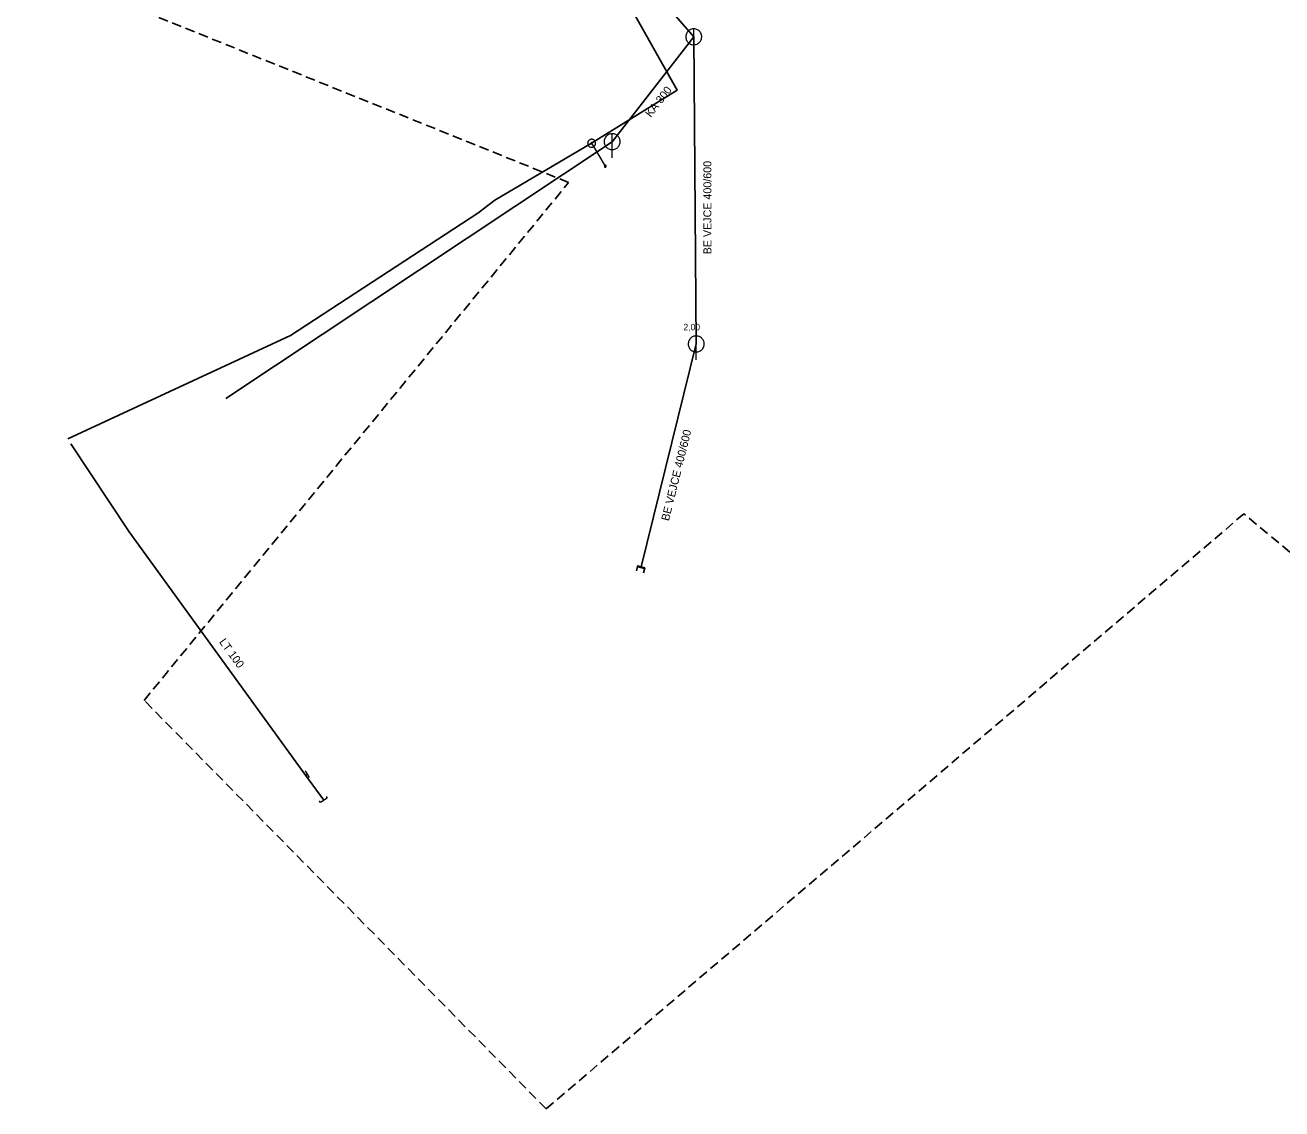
# Model space of a CAD drawing. Extents: x -687195 to -686201, y -974149 to -973877.
# Drawn here: x -687195.2 to -687038.1, y -974149.2 to -974013.8 of the extents above; entities that cross this region are included whole.
import ezdxf

# ---------------------------------------------------------------- set-up
doc = ezdxf.new("R2010")
doc.units = 0
doc.header["$LTSCALE"] = 0.4
doc.linetypes.add('MEDIUM_DASHED', pattern=[4.5, 3, -1.5])
doc.layers.add('1', color=7, linetype='Continuous')
for name, color, linetype, lineweight in [('14', 7, 'Continuous', 25), ('17', 7, 'Continuous', 25), ('22', 7, 'Continuous', 13), ('29', 7, 'Continuous', 13), ('34', 7, 'Continuous', 13), ('47', 7, 'Continuous', 13), ('63', 7, 'MEDIUM_DASHED', 25), ('9', 7, 'Continuous', 13)]:
    doc.layers.add(name, color=color, linetype=linetype, lineweight=lineweight)

msp = doc.modelspace()

# ---------------------------------------------------------------- linework, layer by layer
at = {"layer": '14'}
for p, q in [((-687115.021, -974011.379), (-687111.634, -974015.295)), ((-687111.634, -974015.295), (-687121.836, -974028.397)), ((-687111.634, -974015.295), (-687111.324, -974053.675)), ((-687121.836, -974028.397), (-687170.113, -974060.478)), ((-687111.324, -974053.675), (-687118.2, -974081.535))]:
    msp.add_line(p, q, dxfattribs=at)
at = {"layer": '14', "lineweight": 13}
for p, q in [((-687124.395, -974028.598), (-687122.686, -974031.462)), ((-687160.142, -974107.542), (-687159.94, -974107.42))]:
    msp.add_line(p, q, dxfattribs=at)
at = {"layer": '17'}
for points in [[(-687124.395, -974028.598), (-687113.714, -974021.973), (-687139.989, -973975.271), (-687160.068, -973921.704), (-687165.829, -973892.978), (-687149.548, -973877.175), (-687105.661, -973883.258)], [(-687189.885, -974065.515), (-687162.054, -974052.608), (-687138.614, -974037.32), (-687136.498, -974035.696), (-687124.395, -974028.598)], [(-687189.5, -974066.14), (-687182.219, -974077.149), (-687160.142, -974107.542), (-687157.854, -974110.693)]]:
    msp.add_lwpolyline(points, dxfattribs=at)
at = {"layer": '22'}
for p, q in [((-687111.634, -974017.295), (-687111.633, -974014.295)), ((-687121.836, -974030.397), (-687121.835, -974027.397)), ((-687111.324, -974055.675), (-687111.323, -974052.675))]:
    msp.add_line(p, q, dxfattribs=at)
for points in [[(-687110.634, -974015.295), (-687110.639, -974015.186), (-687110.657, -974015.078), (-687110.687, -974014.972), (-687110.727, -974014.871), (-687110.779, -974014.774), (-687110.841, -974014.684), (-687110.913, -974014.601), (-687110.993, -974014.527), (-687111.081, -974014.461), (-687111.175, -974014.406), (-687111.275, -974014.361), (-687111.38, -974014.328), (-687111.487, -974014.306), (-687111.596, -974014.296), (-687111.706, -974014.298), (-687111.814, -974014.312), (-687111.921, -974014.337), (-687112.024, -974014.374), (-687112.122, -974014.423), (-687112.214, -974014.481), (-687112.3, -974014.55), (-687112.377, -974014.627), (-687112.446, -974014.713), (-687112.505, -974014.805), (-687112.553, -974014.903), (-687112.59, -974015.006), (-687112.616, -974015.113), (-687112.63, -974015.221), (-687112.633, -974015.331), (-687112.623, -974015.44), (-687112.602, -974015.547), (-687112.568, -974015.651), (-687112.524, -974015.751), (-687112.469, -974015.846), (-687112.403, -974015.934), (-687112.329, -974016.014), (-687112.246, -974016.086), (-687112.156, -974016.148), (-687112.06, -974016.2), (-687111.958, -974016.241), (-687111.853, -974016.271), (-687111.745, -974016.289), (-687111.635, -974016.295), (-687111.526, -974016.289), (-687111.418, -974016.271), (-687111.313, -974016.242), (-687111.211, -974016.201), (-687111.114, -974016.149), (-687111.024, -974016.087), (-687110.941, -974016.016), (-687110.866, -974015.936), (-687110.801, -974015.848), (-687110.745, -974015.754), (-687110.701, -974015.654), (-687110.667, -974015.55), (-687110.645, -974015.442), (-687110.635, -974015.333)], [(-687120.836, -974028.397), (-687120.841, -974028.288), (-687120.859, -974028.18), (-687120.889, -974028.074), (-687120.929, -974027.973), (-687120.981, -974027.876), (-687121.043, -974027.786), (-687121.115, -974027.703), (-687121.195, -974027.629), (-687121.283, -974027.563), (-687121.377, -974027.508), (-687121.477, -974027.463), (-687121.582, -974027.43), (-687121.689, -974027.408), (-687121.798, -974027.398), (-687121.908, -974027.4), (-687122.016, -974027.414), (-687122.123, -974027.439), (-687122.226, -974027.476), (-687122.324, -974027.525), (-687122.416, -974027.583), (-687122.502, -974027.652), (-687122.579, -974027.729), (-687122.648, -974027.815), (-687122.707, -974027.907), (-687122.755, -974028.005), (-687122.792, -974028.108), (-687122.818, -974028.215), (-687122.832, -974028.323), (-687122.835, -974028.433), (-687122.825, -974028.542), (-687122.804, -974028.649), (-687122.77, -974028.753), (-687122.726, -974028.853), (-687122.671, -974028.948), (-687122.605, -974029.036), (-687122.531, -974029.116), (-687122.448, -974029.188), (-687122.358, -974029.25), (-687122.262, -974029.302), (-687122.16, -974029.343), (-687122.055, -974029.373), (-687121.947, -974029.391), (-687121.837, -974029.397), (-687121.728, -974029.391), (-687121.62, -974029.373), (-687121.515, -974029.344), (-687121.413, -974029.303), (-687121.316, -974029.251), (-687121.226, -974029.189), (-687121.143, -974029.118), (-687121.068, -974029.038), (-687121.003, -974028.95), (-687120.947, -974028.856), (-687120.903, -974028.756), (-687120.869, -974028.652), (-687120.847, -974028.544), (-687120.837, -974028.435)], [(-687110.324, -974053.675), (-687110.329, -974053.566), (-687110.347, -974053.458), (-687110.377, -974053.352), (-687110.417, -974053.251), (-687110.469, -974053.154), (-687110.531, -974053.064), (-687110.603, -974052.981), (-687110.683, -974052.907), (-687110.771, -974052.841), (-687110.865, -974052.786), (-687110.965, -974052.741), (-687111.07, -974052.708), (-687111.177, -974052.686), (-687111.286, -974052.676), (-687111.396, -974052.678), (-687111.504, -974052.692), (-687111.611, -974052.717), (-687111.714, -974052.754), (-687111.812, -974052.803), (-687111.904, -974052.861), (-687111.99, -974052.93), (-687112.067, -974053.007), (-687112.136, -974053.093), (-687112.195, -974053.185), (-687112.243, -974053.283), (-687112.28, -974053.386), (-687112.306, -974053.493), (-687112.32, -974053.601), (-687112.323, -974053.711), (-687112.313, -974053.82), (-687112.292, -974053.927), (-687112.258, -974054.031), (-687112.214, -974054.131), (-687112.159, -974054.226), (-687112.093, -974054.314), (-687112.019, -974054.394), (-687111.936, -974054.466), (-687111.846, -974054.528), (-687111.75, -974054.58), (-687111.648, -974054.621), (-687111.543, -974054.651), (-687111.435, -974054.669), (-687111.325, -974054.675), (-687111.216, -974054.669), (-687111.108, -974054.651), (-687111.003, -974054.622), (-687110.901, -974054.581), (-687110.804, -974054.529), (-687110.714, -974054.467), (-687110.631, -974054.396), (-687110.556, -974054.316), (-687110.491, -974054.228), (-687110.435, -974054.134), (-687110.391, -974054.034), (-687110.357, -974053.93), (-687110.335, -974053.822), (-687110.325, -974053.713)]]:
    msp.add_lwpolyline(points, close=True, dxfattribs=at)
at = {"layer": '29'}
for points in [[(-687117.865, -974082.256), (-687117.718, -974081.653), (-687118.681, -974081.417), (-687118.829, -974082.022)], [(-687118.744, -974082.042), (-687118.618, -974081.522), (-687117.823, -974081.716), (-687117.95, -974082.236)]]:
    msp.add_lwpolyline(points, dxfattribs=at)
at = {"layer": '34'}
msp.add_line((-687160.199, -974106.992), (-687159.681, -974107.848), dxfattribs=at)
at = {"layer": '47'}
for points in [[(-687123.986, -974028.309), (-687124.019, -974028.268), (-687124.055, -974028.23), (-687124.095, -974028.198), (-687124.138, -974028.168), (-687124.185, -974028.143), (-687124.234, -974028.124), (-687124.284, -974028.111), (-687124.336, -974028.102), (-687124.387, -974028.098), (-687124.44, -974028.1), (-687124.492, -974028.107), (-687124.543, -974028.121), (-687124.592, -974028.138), (-687124.639, -974028.162), (-687124.683, -974028.189), (-687124.724, -974028.222), (-687124.762, -974028.258), (-687124.795, -974028.299), (-687124.824, -974028.341), (-687124.849, -974028.388), (-687124.868, -974028.437), (-687124.882, -974028.488), (-687124.891, -974028.539), (-687124.895, -974028.591), (-687124.892, -974028.643), (-687124.885, -974028.695), (-687124.872, -974028.746), (-687124.854, -974028.795), (-687124.83, -974028.842), (-687124.803, -974028.886), (-687124.77, -974028.927), (-687124.734, -974028.965), (-687124.694, -974028.999), (-687124.651, -974029.027), (-687124.604, -974029.052), (-687124.556, -974029.071), (-687124.505, -974029.086), (-687124.454, -974029.095), (-687124.401, -974029.098), (-687124.349, -974029.095), (-687124.297, -974029.088), (-687124.247, -974029.076), (-687124.197, -974029.057), (-687124.15, -974029.033), (-687124.106, -974029.006), (-687124.065, -974028.973), (-687124.027, -974028.937), (-687123.994, -974028.897), (-687123.965, -974028.854), (-687123.94, -974028.807), (-687123.921, -974028.759), (-687123.907, -974028.709), (-687123.898, -974028.657), (-687123.895, -974028.605), (-687123.897, -974028.552), (-687123.904, -974028.5), (-687123.917, -974028.45), (-687123.935, -974028.4), (-687123.959, -974028.353)], [(-687124.328, -974028.55), (-687124.333, -974028.543), (-687124.339, -974028.537), (-687124.345, -974028.532), (-687124.352, -974028.527), (-687124.36, -974028.523), (-687124.368, -974028.52), (-687124.376, -974028.517), (-687124.385, -974028.516), (-687124.393, -974028.516), (-687124.402, -974028.516), (-687124.411, -974028.517), (-687124.419, -974028.519), (-687124.427, -974028.522), (-687124.434, -974028.525), (-687124.442, -974028.531), (-687124.449, -974028.536), (-687124.455, -974028.542), (-687124.46, -974028.548), (-687124.465, -974028.555), (-687124.469, -974028.563), (-687124.472, -974028.571), (-687124.475, -974028.579), (-687124.476, -974028.588), (-687124.477, -974028.597), (-687124.476, -974028.605), (-687124.475, -974028.614), (-687124.473, -974028.622), (-687124.47, -974028.63), (-687124.467, -974028.637), (-687124.461, -974028.645), (-687124.456, -974028.652), (-687124.45, -974028.658), (-687124.444, -974028.663), (-687124.437, -974028.668), (-687124.429, -974028.672), (-687124.422, -974028.675), (-687124.413, -974028.678), (-687124.404, -974028.679), (-687124.395, -974028.68), (-687124.387, -974028.679), (-687124.378, -974028.678), (-687124.37, -974028.676), (-687124.362, -974028.673), (-687124.355, -974028.67), (-687124.347, -974028.664), (-687124.34, -974028.659), (-687124.334, -974028.653), (-687124.329, -974028.647), (-687124.324, -974028.64), (-687124.32, -974028.632), (-687124.317, -974028.625), (-687124.314, -974028.616), (-687124.313, -974028.607), (-687124.313, -974028.599), (-687124.313, -974028.59), (-687124.314, -974028.581), (-687124.316, -974028.573), (-687124.319, -974028.565), (-687124.322, -974028.558)]]:
    msp.add_lwpolyline(points, close=True, dxfattribs=at)
msp.add_lwpolyline([(-687157.576, -974110.21), (-687157.438, -974110.421), (-687158.269, -974110.964), (-687158.407, -974110.753)], dxfattribs=at)
at = {"layer": '63'}
msp.add_lwpolyline([(-687195.201, -974006.159), (-687144.96, -973932.203), (-687144.96, -973932.203), (-687091.904, -973898.039), (-687091.904, -973898.039), (-686884.104, -974051.176), (-686884.104, -974051.176), (-686970.922, -974135.181), (-686970.922, -974135.181), (-687042.868, -974074.89), (-687042.868, -974074.89), (-687130.088, -974149.248), (-687130.088, -974149.248), (-687180.33, -974098.203), (-687180.33, -974098.203), (-687127.274, -974033.491), (-687127.274, -974033.491)], close=True, dxfattribs=at)
at = {"layer": '9'}
for points in [[(-687122.812, -974031.462), (-687122.812, -974031.475), (-687122.809, -974031.488), (-687122.807, -974031.501), (-687122.802, -974031.513), (-687122.796, -974031.525), (-687122.789, -974031.536), (-687122.781, -974031.546), (-687122.771, -974031.556), (-687122.761, -974031.564), (-687122.75, -974031.571), (-687122.738, -974031.577), (-687122.726, -974031.582), (-687122.713, -974031.585), (-687122.7, -974031.587), (-687122.687, -974031.589), (-687122.674, -974031.588), (-687122.661, -974031.586), (-687122.648, -974031.583), (-687122.636, -974031.578), (-687122.624, -974031.572), (-687122.613, -974031.565), (-687122.603, -974031.557), (-687122.593, -974031.547), (-687122.585, -974031.537), (-687122.578, -974031.526), (-687122.572, -974031.514), (-687122.567, -974031.502), (-687122.564, -974031.489), (-687122.562, -974031.476), (-687122.559, -974031.463), (-687122.561, -974031.45), (-687122.563, -974031.437), (-687122.566, -974031.424), (-687122.571, -974031.412), (-687122.576, -974031.4), (-687122.584, -974031.389), (-687122.592, -974031.379), (-687122.602, -974031.369), (-687122.612, -974031.361), (-687122.623, -974031.354), (-687122.635, -974031.348), (-687122.647, -974031.343), (-687122.66, -974031.34), (-687122.673, -974031.338), (-687122.686, -974031.337), (-687122.699, -974031.337), (-687122.712, -974031.339), (-687122.725, -974031.342), (-687122.737, -974031.347), (-687122.749, -974031.353), (-687122.76, -974031.36), (-687122.77, -974031.368), (-687122.78, -974031.378), (-687122.788, -974031.388), (-687122.795, -974031.399), (-687122.801, -974031.411), (-687122.806, -974031.423), (-687122.809, -974031.436), (-687122.811, -974031.449)], [(-687122.792, -974031.462), (-687122.793, -974031.473), (-687122.791, -974031.484), (-687122.788, -974031.495), (-687122.784, -974031.505), (-687122.779, -974031.515), (-687122.773, -974031.524), (-687122.766, -974031.533), (-687122.758, -974031.541), (-687122.749, -974031.548), (-687122.74, -974031.554), (-687122.73, -974031.559), (-687122.72, -974031.563), (-687122.709, -974031.566), (-687122.698, -974031.569), (-687122.687, -974031.569), (-687122.676, -974031.569), (-687122.665, -974031.567), (-687122.654, -974031.564), (-687122.644, -974031.56), (-687122.634, -974031.555), (-687122.625, -974031.549), (-687122.616, -974031.542), (-687122.608, -974031.534), (-687122.601, -974031.525), (-687122.595, -974031.516), (-687122.59, -974031.506), (-687122.586, -974031.496), (-687122.583, -974031.485), (-687122.581, -974031.474), (-687122.58, -974031.463), (-687122.58, -974031.452), (-687122.581, -974031.441), (-687122.585, -974031.43), (-687122.589, -974031.42), (-687122.594, -974031.41), (-687122.6, -974031.401), (-687122.607, -974031.392), (-687122.615, -974031.384), (-687122.624, -974031.377), (-687122.633, -974031.371), (-687122.643, -974031.366), (-687122.652, -974031.362), (-687122.664, -974031.359), (-687122.674, -974031.357), (-687122.686, -974031.357), (-687122.697, -974031.356), (-687122.708, -974031.358), (-687122.719, -974031.361), (-687122.728, -974031.365), (-687122.739, -974031.37), (-687122.748, -974031.376), (-687122.757, -974031.383), (-687122.765, -974031.391), (-687122.772, -974031.4), (-687122.777, -974031.409), (-687122.782, -974031.419), (-687122.787, -974031.429), (-687122.79, -974031.44), (-687122.792, -974031.451)], [(-687122.773, -974031.462), (-687122.773, -974031.471), (-687122.772, -974031.48), (-687122.769, -974031.489), (-687122.766, -974031.497), (-687122.762, -974031.505), (-687122.757, -974031.513), (-687122.75, -974031.52), (-687122.745, -974031.526), (-687122.738, -974031.532), (-687122.73, -974031.537), (-687122.722, -974031.541), (-687122.714, -974031.544), (-687122.705, -974031.547), (-687122.696, -974031.548), (-687122.687, -974031.55), (-687122.678, -974031.549), (-687122.669, -974031.548), (-687122.66, -974031.545), (-687122.652, -974031.542), (-687122.644, -974031.538), (-687122.636, -974031.533), (-687122.629, -974031.527), (-687122.623, -974031.521), (-687122.617, -974031.514), (-687122.612, -974031.506), (-687122.608, -974031.498), (-687122.605, -974031.49), (-687122.602, -974031.481), (-687122.601, -974031.472), (-687122.598, -974031.463), (-687122.6, -974031.454), (-687122.601, -974031.445), (-687122.603, -974031.436), (-687122.607, -974031.428), (-687122.611, -974031.42), (-687122.616, -974031.412), (-687122.622, -974031.405), (-687122.628, -974031.399), (-687122.635, -974031.393), (-687122.643, -974031.388), (-687122.651, -974031.384), (-687122.659, -974031.381), (-687122.668, -974031.378), (-687122.677, -974031.377), (-687122.686, -974031.376), (-687122.695, -974031.376), (-687122.704, -974031.377), (-687122.713, -974031.38), (-687122.721, -974031.383), (-687122.728, -974031.387), (-687122.737, -974031.392), (-687122.744, -974031.398), (-687122.75, -974031.404), (-687122.755, -974031.411), (-687122.761, -974031.419), (-687122.765, -974031.427), (-687122.768, -974031.435), (-687122.771, -974031.444), (-687122.772, -974031.453)], [(-687122.753, -974031.462), (-687122.753, -974031.469), (-687122.752, -974031.476), (-687122.75, -974031.483), (-687122.748, -974031.489), (-687122.745, -974031.495), (-687122.741, -974031.501), (-687122.737, -974031.507), (-687122.732, -974031.512), (-687122.726, -974031.516), (-687122.72, -974031.52), (-687122.714, -974031.523), (-687122.708, -974031.526), (-687122.701, -974031.527), (-687122.694, -974031.53), (-687122.687, -974031.53), (-687122.679, -974031.53), (-687122.673, -974031.528), (-687122.666, -974031.527), (-687122.66, -974031.524), (-687122.652, -974031.521), (-687122.648, -974031.517), (-687122.642, -974031.513), (-687122.637, -974031.508), (-687122.633, -974031.502), (-687122.629, -974031.496), (-687122.625, -974031.49), (-687122.623, -974031.484), (-687122.621, -974031.477), (-687122.62, -974031.47), (-687122.619, -974031.463), (-687122.619, -974031.456), (-687122.62, -974031.449), (-687122.622, -974031.442), (-687122.625, -974031.436), (-687122.628, -974031.429), (-687122.632, -974031.424), (-687122.636, -974031.418), (-687122.641, -974031.413), (-687122.647, -974031.409), (-687122.652, -974031.405), (-687122.659, -974031.402), (-687122.665, -974031.399), (-687122.672, -974031.397), (-687122.679, -974031.396), (-687122.686, -974031.396), (-687122.693, -974031.396), (-687122.7, -974031.396), (-687122.706, -974031.398), (-687122.713, -974031.401), (-687122.719, -974031.404), (-687122.725, -974031.408), (-687122.731, -974031.412), (-687122.736, -974031.417), (-687122.74, -974031.423), (-687122.744, -974031.428), (-687122.747, -974031.435), (-687122.75, -974031.441), (-687122.75, -974031.448), (-687122.753, -974031.455)], [(-687122.733, -974031.462), (-687122.733, -974031.467), (-687122.733, -974031.472), (-687122.732, -974031.477), (-687122.73, -974031.481), (-687122.728, -974031.486), (-687122.725, -974031.49), (-687122.722, -974031.493), (-687122.718, -974031.497), (-687122.715, -974031.5), (-687122.711, -974031.503), (-687122.706, -974031.505), (-687122.701, -974031.507), (-687122.697, -974031.508), (-687122.692, -974031.51), (-687122.687, -974031.51), (-687122.682, -974031.51), (-687122.677, -974031.509), (-687122.672, -974031.508), (-687122.668, -974031.506), (-687122.663, -974031.504), (-687122.659, -974031.501), (-687122.655, -974031.498), (-687122.652, -974031.494), (-687122.649, -974031.491), (-687122.646, -974031.487), (-687122.644, -974031.482), (-687122.642, -974031.478), (-687122.641, -974031.473), (-687122.64, -974031.468), (-687122.639, -974031.463), (-687122.639, -974031.458), (-687122.64, -974031.453), (-687122.641, -974031.448), (-687122.643, -974031.444), (-687122.645, -974031.439), (-687122.648, -974031.435), (-687122.651, -974031.431), (-687122.654, -974031.428), (-687122.657, -974031.425), (-687122.662, -974031.422), (-687122.667, -974031.42), (-687122.671, -974031.418), (-687122.676, -974031.417), (-687122.681, -974031.416), (-687122.686, -974031.416), (-687122.691, -974031.416), (-687122.696, -974031.417), (-687122.701, -974031.417), (-687122.705, -974031.419), (-687122.71, -974031.421), (-687122.714, -974031.424), (-687122.717, -974031.427), (-687122.721, -974031.43), (-687122.723, -974031.434), (-687122.727, -974031.438), (-687122.728, -974031.443), (-687122.731, -974031.447), (-687122.732, -974031.452), (-687122.733, -974031.457)], [(-687122.713, -974031.462), (-687122.713, -974031.465), (-687122.714, -974031.468), (-687122.713, -974031.47), (-687122.712, -974031.473), (-687122.711, -974031.476), (-687122.709, -974031.478), (-687122.706, -974031.48), (-687122.705, -974031.482), (-687122.703, -974031.484), (-687122.701, -974031.486), (-687122.698, -974031.488), (-687122.695, -974031.489), (-687122.693, -974031.489), (-687122.69, -974031.49), (-687122.687, -974031.49), (-687122.684, -974031.49), (-687122.681, -974031.49), (-687122.678, -974031.489), (-687122.676, -974031.488), (-687122.673, -974031.487), (-687122.671, -974031.485), (-687122.668, -974031.483), (-687122.666, -974031.481), (-687122.665, -974031.479), (-687122.663, -974031.477), (-687122.662, -974031.474), (-687122.66, -974031.471), (-687122.66, -974031.469), (-687122.659, -974031.466), (-687122.657, -974031.463), (-687122.659, -974031.46), (-687122.659, -974031.457), (-687122.66, -974031.454), (-687122.661, -974031.452), (-687122.662, -974031.449), (-687122.664, -974031.447), (-687122.665, -974031.444), (-687122.667, -974031.442), (-687122.67, -974031.441), (-687122.672, -974031.439), (-687122.674, -974031.438), (-687122.677, -974031.437), (-687122.679, -974031.436), (-687122.683, -974031.436), (-687122.686, -974031.435), (-687122.689, -974031.436), (-687122.692, -974031.435), (-687122.694, -974031.437), (-687122.697, -974031.437), (-687122.7, -974031.438), (-687122.701, -974031.44), (-687122.704, -974031.441), (-687122.706, -974031.443), (-687122.708, -974031.446), (-687122.71, -974031.448), (-687122.711, -974031.451), (-687122.712, -974031.453), (-687122.713, -974031.456), (-687122.713, -974031.459)], [(-687122.694, -974031.462), (-687122.694, -974031.464), (-687122.694, -974031.464), (-687122.693, -974031.464), (-687122.693, -974031.466), (-687122.694, -974031.467), (-687122.692, -974031.467), (-687122.692, -974031.467), (-687122.692, -974031.469), (-687122.692, -974031.469), (-687122.691, -974031.47), (-687122.689, -974031.47), (-687122.689, -974031.47), (-687122.689, -974031.471), (-687122.687, -974031.471), (-687122.687, -974031.471), (-687122.686, -974031.471), (-687122.684, -974031.471), (-687122.684, -974031.47), (-687122.684, -974031.47), (-687122.682, -974031.47), (-687122.682, -974031.469), (-687122.682, -974031.469), (-687122.681, -974031.468), (-687122.681, -974031.468), (-687122.679, -974031.467), (-687122.679, -974031.466), (-687122.678, -974031.465), (-687122.678, -974031.465), (-687122.678, -974031.464), (-687122.678, -974031.463), (-687122.678, -974031.462), (-687122.678, -974031.461), (-687122.678, -974031.461), (-687122.679, -974031.46), (-687122.679, -974031.459), (-687122.679, -974031.458), (-687122.679, -974031.458), (-687122.681, -974031.457), (-687122.681, -974031.457), (-687122.682, -974031.456), (-687122.683, -974031.456), (-687122.684, -974031.455), (-687122.684, -974031.455), (-687122.684, -974031.455), (-687122.686, -974031.455), (-687122.687, -974031.455), (-687122.688, -974031.455), (-687122.688, -974031.455), (-687122.689, -974031.456), (-687122.69, -974031.455), (-687122.691, -974031.457), (-687122.691, -974031.457), (-687122.692, -974031.457), (-687122.692, -974031.457), (-687122.693, -974031.459), (-687122.693, -974031.46), (-687122.693, -974031.461), (-687122.694, -974031.461), (-687122.694, -974031.462)]]:
    msp.add_lwpolyline(points, close=True, dxfattribs=at)

# ---------------------------------------------------------------- texts
at = {"layer": '1'}
for s, rotation, p in [('KA 300', 52, (-687117.011, -974025.432)), ('BE VEJCE 400/600', 90, (-687109.429, -974042.468)), ('BE VEJCE 400/600', 76, (-687114.751, -974075.847)), ('LT 100', 306, (-687171.002, -974090.914))]:
    msp.add_text(s, height=1, rotation=rotation, dxfattribs=at).set_placement(p)
msp.add_text('2,00', height=0.8, dxfattribs=at).set_placement((-687112.924, -974051.963))

doc.saveas('drawing.dxf')
